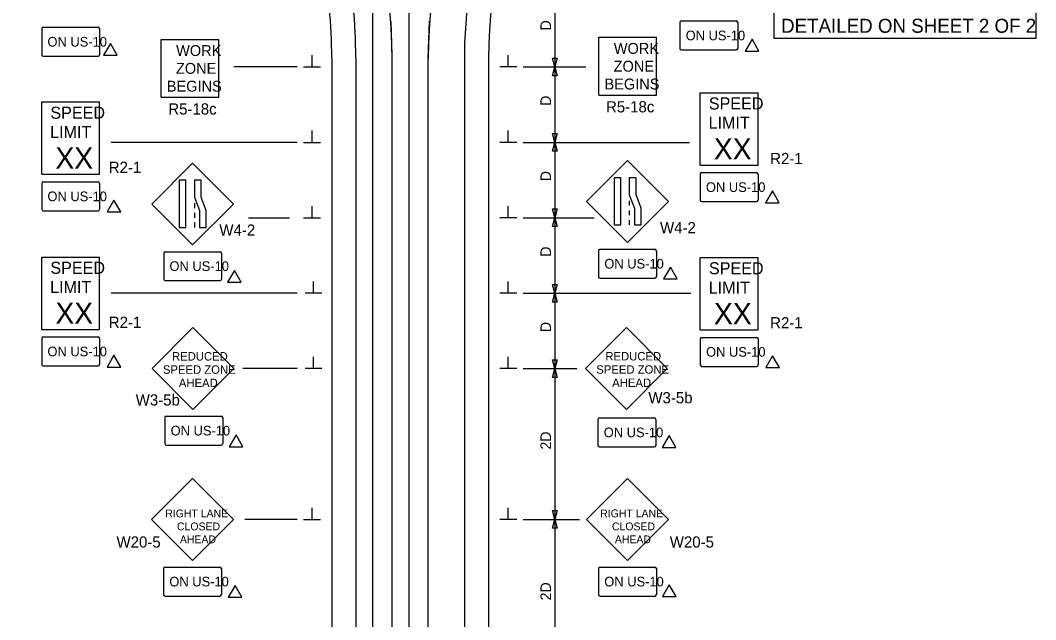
# Model space of a CAD drawing. Extents: x 16556 to 18479, y 5704 to 6974.
# Drawn here: x 16747 to 17421, y 6153 to 6550 of the extents above; entities that cross this region are included whole.
import ezdxf

# ---------------------------------------------------------------- set-up
doc = ezdxf.new("R2010")
doc.units = 0
for name, color, linetype in [('ALI_LEGAL_EX', 7, 'Continuous'), ('PAVT_EDGE_EX', 7, 'Continuous'), ('TRAFFIC_SIGNS_PR', 7, 'Continuous'), ('TYPICAL_TEXT_DIMEN_EX', 7, 'Continuous'), ('TYPICAL_TEXT_DIMEN_PR', 7, 'Continuous')]:
    doc.layers.add(name, color=color, linetype=linetype)

msp = doc.modelspace()

# ---------------------------------------------------------------- linework, layer by layer
at = {"layer": 'ALI_LEGAL_EX'}
for p, q in [((16980.68, 6974.12), (16980.68, 6155.98)), ((17004.68, 6974.12), (17004.68, 6155.98)), ((16980.68, 6877.04), (16980.68, 6013.12)), ((17004.68, 6877.04), (17004.68, 6013.12)), ((16993.65, 6024.8), (16993.65, 6525.15)), ((17017.65, 6024.8), (17017.65, 6525.15))]:
    msp.add_line(p, q, dxfattribs=at)
for points in [[(16993.6, 6524.8), (16993.65, 6525.15), (16993.08, 6549.79)], [(17017.7, 6524.8), (17017.65, 6525.15), (17018.48, 6549.78)], [(16993.65, 6424.8), (16993.65, 6449.8)], [(17017.65, 6424.8), (17017.65, 6449.8)], [(16993.65, 6324.8), (16993.65, 6349.8)], [(17017.65, 6324.8), (17017.65, 6349.8)], [(16993.65, 6224.8), (16993.65, 6249.8)], [(17017.65, 6224.8), (17017.65, 6249.8)]]:
    msp.add_lwpolyline(points, dxfattribs=at)
for centre, radius, start, end in [((16629.65, 6525.15), 364, 0, 57.29578), ((17357.65, 6525.15), 340, 129.56655, 180)]:
    msp.add_arc(centre, radius, start, end, dxfattribs=at)
at = {"layer": 'PAVT_EDGE_EX'}
for p, q in [((16953.65, 6525.15), (16953.65, 6062.71)), ((16969.65, 6525.15), (16969.65, 6062.71)), ((17041.65, 6525.15), (17041.65, 6062.71)), ((17057.65, 6525.15), (17057.65, 6062.71))]:
    msp.add_line(p, q, dxfattribs=at)
for centre, radius, start, end in [((16629.65, 6525.15), 340, 0, 68.7791), ((16629.65, 6525.15), 324, 0, 68.7791), ((17357.65, 6525.15), 316, 123.6935, 180), ((17357.65, 6525.15), 300, 123.6935, 180), ((17357.65, 6525.15), 300, 180, 180.00000277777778), ((17357.65, 6475.15), 300, 180, 180.00000277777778)]:
    msp.add_arc(centre, radius, start, end, dxfattribs=at)
at = {"layer": 'TRAFFIC_SIGNS_PR'}
for p, q in [((17185.62, 6549.81), (17222.02, 6549.81)), ((16761.11, 6544.64), (16761.11, 6527.44)), ((16762.11, 6545.64), (16798.51, 6545.64)), ((16799.51, 6544.64), (16799.51, 6527.44)), ((17184.62, 6548.81), (17184.62, 6531.61)), ((17223.02, 6548.81), (17223.02, 6531.61)), ((16840.32, 6499.23), (16840.32, 6537.63)), ((16840.32, 6537.63), (16878.72, 6537.63)), ((16878.72, 6499.23), (16878.72, 6537.63)), ((17130.79, 6500.65), (17130.79, 6539.05)), ((17130.79, 6539.05), (17169.19, 6539.05)), ((17169.19, 6500.65), (17169.19, 6539.05)), ((17185.62, 6530.61), (17222.02, 6530.61)), ((16762.11, 6526.44), (16798.51, 6526.44)), ((16761.11, 6496.15), (16799.51, 6496.15)), ((16761.11, 6448.15), (16761.11, 6496.15)), ((16799.51, 6448.15), (16799.51, 6496.15)), ((16840.32, 6499.23), (16878.72, 6499.23)), ((17130.79, 6500.65), (17169.19, 6500.65)), ((17198.08, 6502.27), (17236.48, 6502.27)), ((17198.08, 6454.27), (17198.08, 6502.27)), ((17236.48, 6454.27), (17236.48, 6502.27)), ((16861.27, 6455.62), (16834.12, 6428.47)), ((16888.42, 6428.47), (16861.27, 6455.62)), ((17149.84, 6457.24), (17122.69, 6430.09)), ((17176.99, 6430.09), (17149.84, 6457.24)), ((17198.08, 6454.27), (17236.48, 6454.27)), ((17199.08, 6449.27), (17235.48, 6449.27)), ((16761.11, 6448.15), (16799.51, 6448.15)), ((16761.11, 6442.15), (16761.11, 6424.95)), ((16762.11, 6443.15), (16798.51, 6443.15)), ((16799.51, 6442.15), (16799.51, 6424.95)), ((17198.08, 6448.27), (17198.08, 6431.07)), ((17236.48, 6448.27), (17236.48, 6431.07)), ((16834.12, 6428.47), (16861.27, 6401.31)), ((16861.27, 6401.31), (16888.42, 6428.47)), ((16862.51, 6428.96), (16862.51, 6425.76)), ((17122.69, 6430.09), (17149.84, 6402.93)), ((17149.84, 6402.93), (17176.99, 6430.09)), ((17151.08, 6430.58), (17151.08, 6427.38)), ((17199.08, 6430.07), (17235.48, 6430.07)), ((16762.11, 6423.95), (16798.51, 6423.95)), ((16862.51, 6422.56), (16862.51, 6419.36)), ((17151.08, 6424.18), (17151.08, 6420.98)), ((16862.51, 6416.16), (16862.51, 6412.96)), ((17151.08, 6417.78), (17151.08, 6414.58)), ((16842.07, 6395.87), (16842.07, 6378.67)), ((16843.07, 6396.87), (16879.47, 6396.87)), ((16880.47, 6395.87), (16880.47, 6378.67)), ((17130.64, 6397.49), (17130.64, 6380.28)), ((17131.64, 6398.49), (17168.04, 6398.49)), ((17169.04, 6397.49), (17169.04, 6380.28)), ((16761.11, 6393.31), (16799.51, 6393.31)), ((16761.11, 6345.31), (16761.11, 6393.31)), ((16799.51, 6345.31), (16799.51, 6393.31)), ((17198.16, 6393.03), (17236.56, 6393.03)), ((17198.16, 6345.03), (17198.16, 6393.03)), ((17236.56, 6345.03), (17236.56, 6393.03)), ((16843.07, 6377.67), (16879.47, 6377.67)), ((17131.64, 6379.28), (17168.04, 6379.28)), ((16761.11, 6345.31), (16799.51, 6345.31)), ((16861.52, 6346.53), (16834.37, 6319.38)), ((16888.68, 6319.38), (16861.52, 6346.53)), ((17149.1, 6346.61), (17121.95, 6319.46)), ((17176.25, 6319.46), (17149.1, 6346.61)), ((17198.16, 6345.03), (17236.56, 6345.03)), ((16761.11, 6339.31), (16761.11, 6322.11)), ((16762.11, 6340.31), (16798.51, 6340.31)), ((16799.51, 6339.31), (16799.51, 6322.11)), ((17198.16, 6339.03), (17198.16, 6321.83)), ((17199.16, 6340.03), (17235.56, 6340.03)), ((17236.56, 6339.03), (17236.56, 6321.83)), ((16762.11, 6321.11), (16798.51, 6321.11)), ((17199.16, 6320.83), (17235.56, 6320.83)), ((16834.37, 6319.38), (16861.52, 6292.22)), ((16861.52, 6292.22), (16888.68, 6319.38)), ((17121.95, 6319.46), (17149.1, 6292.3)), ((17149.1, 6292.3), (17176.25, 6319.46)), ((16842.86, 6286.82), (16842.86, 6269.62)), ((16843.86, 6287.82), (16880.26, 6287.82)), ((16881.26, 6286.82), (16881.26, 6269.62)), ((17130.27, 6285.67), (17130.27, 6268.47)), ((17131.27, 6286.67), (17167.67, 6286.67)), ((17168.67, 6285.67), (17168.67, 6268.47)), ((16843.86, 6268.62), (16880.26, 6268.62)), ((17131.27, 6267.47), (17167.67, 6267.47)), ((16861.18, 6246.49), (16834.02, 6219.33)), ((16888.34, 6219.33), (16861.18, 6246.49)), ((17149.82, 6246.49), (17122.67, 6219.33)), ((17176.98, 6219.33), (17149.82, 6246.49)), ((16834.02, 6219.33), (16861.18, 6192.17)), ((16861.18, 6192.17), (16888.34, 6219.33)), ((17122.67, 6219.33), (17149.82, 6192.17)), ((17149.82, 6192.17), (17176.98, 6219.33)), ((16841.98, 6186.73), (16841.98, 6169.53)), ((16842.98, 6187.73), (16879.38, 6187.73)), ((16880.38, 6186.73), (16880.38, 6169.53)), ((17130.62, 6186.73), (17130.62, 6169.53)), ((17131.62, 6187.73), (17168.03, 6187.73)), ((17169.03, 6186.73), (17169.03, 6169.53)), ((16842.98, 6168.53), (16879.38, 6168.53)), ((17131.62, 6168.53), (17168.03, 6168.53))]:
    msp.add_line(p, q, dxfattribs=at)
for points in [[(16852.37, 6444.2), (16852.37, 6412.96), (16856.87, 6412.96), (16856.87, 6444.2)], [(16862.51, 6444.2), (16862.51, 6433.02), (16865.85, 6424.14), (16865.85, 6412.96), (16870.35, 6412.96), (16870.35, 6424.14), (16867, 6433.02), (16867, 6444.2)], [(17140.94, 6445.82), (17140.94, 6414.58), (17145.44, 6414.58), (17145.44, 6445.82)], [(17151.08, 6445.82), (17151.08, 6434.64), (17154.42, 6425.76), (17154.42, 6414.58), (17158.92, 6414.58), (17158.92, 6425.76), (17155.57, 6434.64), (17155.57, 6445.82)]]:
    msp.add_lwpolyline(points, close=True, dxfattribs=at)
for centre, start, end in [((17185.62, 6548.81), 90, 180), ((17222.02, 6548.81), 0, 90), ((16762.11, 6544.64), 90, 180), ((16798.51, 6544.64), 0, 90), ((17185.62, 6531.61), 180, 270), ((17222.02, 6531.61), 270, 0), ((16762.11, 6527.44), 180, 270), ((16798.51, 6527.44), 270, 0), ((17199.08, 6448.27), 90, 180), ((17235.48, 6448.27), 0, 90), ((16762.11, 6442.15), 90, 180), ((16798.51, 6442.15), 0, 90), ((17199.08, 6431.07), 180, 270), ((17235.48, 6431.07), 270, 0), ((16762.11, 6424.95), 180, 270), ((16798.51, 6424.95), 270, 0), ((16843.07, 6395.87), 90, 180), ((16879.47, 6395.87), 0, 90), ((17131.64, 6397.49), 90, 180), ((17168.04, 6397.49), 0, 90), ((16843.07, 6378.67), 180, 270), ((16879.47, 6378.67), 270, 0), ((17131.64, 6380.28), 180, 270), ((17168.04, 6380.28), 270, 0), ((16762.1, 6339.31), 90, 180), ((16798.5, 6339.31), 0, 90), ((17199.16, 6339.03), 90, 180), ((17235.56, 6339.03), 0, 90), ((16762.1, 6322.11), 180, 270), ((16798.5, 6322.11), 270, 0), ((17199.16, 6321.83), 180, 270), ((17235.56, 6321.83), 270, 0), ((16843.86, 6286.82), 90, 180), ((16880.26, 6286.82), 0, 90), ((17131.27, 6285.67), 90, 180), ((17167.67, 6285.67), 0, 90), ((16843.86, 6269.62), 180, 270), ((16880.26, 6269.62), 270, 0), ((17131.27, 6268.47), 180, 270), ((17167.67, 6268.47), 270, 0), ((16842.98, 6186.73), 90, 180), ((16879.38, 6186.73), 0, 90), ((17131.62, 6186.73), 90, 180), ((17168.02, 6186.73), 0, 90), ((16842.98, 6169.53), 180, 270), ((16879.38, 6169.53), 270, 0), ((17131.62, 6169.53), 180, 270), ((17168.02, 6169.53), 270, 0)]:
    msp.add_arc(centre, 1, start, end, dxfattribs=at)
at = {"layer": 'TYPICAL_TEXT_DIMEN_EX'}
msp.add_lwpolyline([(17247.1, 6620.06), (17420.75, 6620.06), (17420.75, 6538.3), (17247.1, 6538.3)], close=True, dxfattribs=at)
at = {"layer": 'TYPICAL_TEXT_DIMEN_PR'}
for p, q in [((17101.65, 6569.33), (17101.65, 6519.33)), ((16940.52, 6519.33), (16940.52, 6527.11)), ((17070.77, 6519.33), (17070.77, 6527.11)), ((17101.65, 6519.33), (17100.08, 6525.19)), ((17100.08, 6525.19), (17101.65, 6525.19)), ((17101.65, 6525.19), (17103.22, 6525.19)), ((17103.22, 6525.19), (17101.65, 6519.33)), ((16930.65, 6519.33), (16888.72, 6519.33)), ((16934.9, 6519.33), (16946.15, 6519.33)), ((17076.4, 6519.33), (17065.15, 6519.33)), ((17080.65, 6519.33), (17122.2, 6519.33)), ((17100.08, 6513.47), (17101.65, 6519.33)), ((17101.65, 6519.33), (17103.22, 6513.47)), ((17101.65, 6519.33), (17101.65, 6469.33)), ((17101.65, 6513.47), (17100.08, 6513.47)), ((17103.22, 6513.47), (17101.65, 6513.47)), ((16940.52, 6469.33), (16940.52, 6477.11)), ((17070.77, 6469.33), (17070.77, 6477.11)), ((16930.65, 6469.33), (16807.28, 6469.33)), ((16934.9, 6469.33), (16946.15, 6469.33)), ((17076.4, 6469.33), (17065.15, 6469.33)), ((17080.65, 6469.33), (17191.06, 6469.33)), ((17101.65, 6469.33), (17100.08, 6475.19)), ((17100.08, 6475.19), (17101.65, 6475.19)), ((17100.08, 6463.47), (17101.65, 6469.33)), ((17101.65, 6475.19), (17103.22, 6475.19)), ((17103.22, 6475.19), (17101.65, 6469.33)), ((17101.65, 6469.33), (17101.65, 6419.33)), ((17101.65, 6469.33), (17103.22, 6463.47)), ((17101.65, 6463.47), (17100.08, 6463.47)), ((17103.22, 6463.47), (17101.65, 6463.47)), ((16940.52, 6419.33), (16940.52, 6427.11)), ((17070.77, 6419.33), (17070.77, 6427.11)), ((17101.65, 6419.33), (17100.08, 6425.19)), ((17100.08, 6425.19), (17101.65, 6425.19)), ((17101.65, 6425.19), (17103.22, 6425.19)), ((17103.22, 6425.19), (17101.65, 6419.33)), ((16898.37, 6419.33), (16925.67, 6419.33)), ((16934.9, 6419.33), (16946.15, 6419.33)), ((17076.4, 6419.33), (17065.15, 6419.33)), ((17080.65, 6419.33), (17127.82, 6419.33)), ((17100.08, 6413.47), (17101.65, 6419.33)), ((17101.65, 6419.33), (17101.65, 6369.33)), ((17101.65, 6419.33), (17103.22, 6413.47)), ((17101.65, 6413.47), (17100.08, 6413.47)), ((17103.22, 6413.47), (17101.65, 6413.47)), ((16941.49, 6369.33), (16941.49, 6377.11)), ((17070.77, 6369.33), (17070.77, 6377.11)), ((17101.65, 6369.33), (17100.08, 6375.19)), ((17100.08, 6375.19), (17101.65, 6375.19)), ((17101.65, 6375.19), (17103.22, 6375.19)), ((17103.22, 6375.19), (17101.65, 6369.33)), ((16930.65, 6369.33), (16807.28, 6369.33)), ((16947.11, 6369.33), (16935.86, 6369.33)), ((17076.4, 6369.33), (17065.15, 6369.33)), ((17080.65, 6369.33), (17191.81, 6369.33)), ((17100.08, 6363.47), (17101.65, 6369.33)), ((17101.65, 6369.33), (17101.65, 6319.33)), ((17101.65, 6369.33), (17103.22, 6363.47)), ((17101.65, 6363.47), (17100.08, 6363.47)), ((17103.22, 6363.47), (17101.65, 6363.47)), ((16941.49, 6319.33), (16941.49, 6327.11)), ((17070.77, 6319.33), (17070.77, 6327.11)), ((17101.65, 6319.33), (17100.08, 6325.19)), ((17100.08, 6325.19), (17101.65, 6325.19)), ((17101.65, 6325.19), (17103.22, 6325.19)), ((17103.22, 6325.19), (17101.65, 6319.33)), ((16930.65, 6319.33), (16894.65, 6319.33)), ((16947.11, 6319.33), (16935.86, 6319.33)), ((17076.4, 6319.33), (17065.15, 6319.33)), ((17080.65, 6319.33), (17116.35, 6319.33)), ((17100.08, 6313.47), (17101.65, 6319.33)), ((17101.65, 6319.33), (17101.65, 6219.33)), ((17101.65, 6319.33), (17103.22, 6313.47)), ((17101.65, 6313.47), (17100.08, 6313.47)), ((17103.22, 6313.47), (17101.65, 6313.47)), ((16940.52, 6219.33), (16940.52, 6227.11)), ((17070.77, 6219.33), (17070.77, 6227.11)), ((17101.65, 6219.33), (17100.08, 6225.19)), ((17100.08, 6225.19), (17101.65, 6225.19)), ((17101.65, 6225.19), (17103.22, 6225.19)), ((17103.22, 6225.19), (17101.65, 6219.33)), ((16930.65, 6219.33), (16895.9, 6219.33)), ((16934.9, 6219.33), (16946.15, 6219.33)), ((17076.4, 6219.33), (17065.15, 6219.33)), ((17080.65, 6219.33), (17117.91, 6219.33)), ((17100.08, 6213.47), (17101.65, 6219.33)), ((17101.65, 6213.47), (17100.08, 6213.47)), ((17101.65, 6219.33), (17101.65, 6119.33)), ((17101.65, 6219.33), (17103.22, 6213.47)), ((17103.22, 6213.47), (17101.65, 6213.47))]:
    msp.add_line(p, q, dxfattribs=at)
for points in [[(17232.57, 6537.67), (17228.04, 6529.84), (17237.09, 6529.84)], [(16806.71, 6534.89), (16802.18, 6527.05), (16811.23, 6527.05)], [(17246.03, 6437.14), (17241.5, 6429.3), (17250.55, 6429.3)], [(16809.05, 6431.01), (16804.53, 6423.18), (16813.58, 6423.18)], [(16888.96, 6384.46), (16884.44, 6376.62), (16893.49, 6376.62)], [(17178.34, 6386.67), (17173.81, 6378.83), (17182.87, 6378.83)], [(16809.05, 6328.17), (16804.53, 6320.34), (16813.58, 6320.34)], [(17246.1, 6327.89), (17241.58, 6320.06), (17250.63, 6320.06)], [(16890.07, 6275.4), (16885.55, 6267.56), (16894.6, 6267.56)], [(17177.47, 6274.92), (17172.95, 6267.08), (17182, 6267.08)], [(16889.43, 6175.62), (16884.91, 6167.79), (16893.96, 6167.79)], [(17177.62, 6175.99), (17173.1, 6168.15), (17182.15, 6168.15)]]:
    msp.add_lwpolyline(points, close=True, dxfattribs=at)

# ---------------------------------------------------------------- texts
at = {"layer": 'TRAFFIC_SIGNS_PR'}
for s, height, p in [('ON US-10', 6.4, (17188.46, 6537.01)), ('ON US-10', 6.4, (16764.94, 6532.84)), ('WORK', 7.217, (16850.32, 6526.6)), ('WORK', 7.217, (17140.79, 6528.02)), ('ZONE', 7.217, (17140.67, 6516.21)), ('ZONE', 7.217, (16850.2, 6514.79)), ('BEGINS', 7.217, (16844.13, 6502.98)), ('BEGINS', 7.217, (17134.6, 6504.4)), ('R5-18c', 7.44, (17135.6, 6489.21)), ('SPEED', 8, (17203.84, 6491.14)), ('SPEED', 8, (16766.87, 6485.01)), ('R5-18c', 7.44, (16845.13, 6487.79)), ('LIMIT', 8, (17203.68, 6478.34)), ('LIMIT', 8, (16766.71, 6472.21)), ('XX', 14.031, (17207.19, 6458.03)), ('XX', 14.031, (16770.22, 6451.91)), ('R2-1', 7.44, (17244.56, 6454.89)), ('R2-1', 7.44, (16805.63, 6449.07)), ('ON US-10', 6.4, (17201.91, 6436.47)), ('ON US-10', 6.4, (16764.94, 6430.35)), ('W4-2', 7.441, (16879.01, 6407.46)), ('W4-2', 7.441, (17171.46, 6409.08)), ('SPEED', 8, (16766.87, 6382.17)), ('ON US-10', 6.401, (16845.91, 6384.07)), ('ON US-10', 6.401, (17134.48, 6385.69)), ('SPEED', 8, (17203.92, 6381.89)), ('LIMIT', 8, (16766.71, 6369.37)), ('LIMIT', 8, (17203.76, 6369.09)), ('XX', 14.031, (16770.22, 6349.07)), ('XX', 14.031, (17207.27, 6348.79)), ('R2-1', 7.44, (16805.63, 6346.34)), ('R2-1', 7.44, (17244.56, 6346.02)), ('ON US-10', 6.4, (16764.94, 6327.51)), ('REDUCED', 5.6, (16847.58, 6324.69)), ('REDUCED', 5.6, (17135.16, 6324.76)), ('ON US-10', 6.4, (17201.99, 6327.23)), ('SPEED ZONE', 5.6, (16841.57, 6315.89)), ('SPEED ZONE', 5.6, (17129.15, 6315.96)), ('AHEAD', 5.6, (16852.14, 6307.09)), ('AHEAD', 5.6, (17139.71, 6307.16)), ('W3-5b', 7.44, (16823.51, 6294.84)), ('W3-5b', 7.44, (17163.73, 6296.33)), ('ON US-10', 6.4, (16846.7, 6275.02)), ('ON US-10', 6.4, (17134.11, 6273.87)), ('RIGHT LANE', 5.201, (16843.1, 6220.73)), ('RIGHT LANE', 5.201, (17131.74, 6220.73)), ('CLOSED', 5.201, (16850.89, 6212.12)), ('CLOSED', 5.201, (17139.53, 6212.12)), ('W20-5', 7.441, (16810.77, 6200.67)), ('AHEAD', 5.201, (16852.84, 6203.52)), ('AHEAD', 5.201, (17141.48, 6203.52)), ('W20-5', 7.441, (17177.92, 6200.67)), ('ON US-10', 6.401, (16845.81, 6174.93)), ('ON US-10', 6.401, (17134.46, 6174.93))]:
    msp.add_text(s, height=height, dxfattribs=at).set_placement(p)
at = {"layer": 'TYPICAL_TEXT_DIMEN_EX'}
msp.add_text('DETAILED ON SHEET 2 OF 2', height=9.3, dxfattribs=at).set_placement((17251.76, 6541.98))
at = {"layer": 'TYPICAL_TEXT_DIMEN_PR'}
for s, p in [('D', (17099.09, 6543.55)), ('D', (17099.09, 6493.55)), ('D', (17099.09, 6443.55)), ('D', (17099.09, 6393.55)), ('D', (17099.09, 6343.55)), ('2D', (17099.09, 6265.69)), ('2D', (17099.09, 6165.69))]:
    msp.add_text(s, height=7, rotation=90, dxfattribs=at).set_placement(p)

doc.saveas('drawing.dxf')
